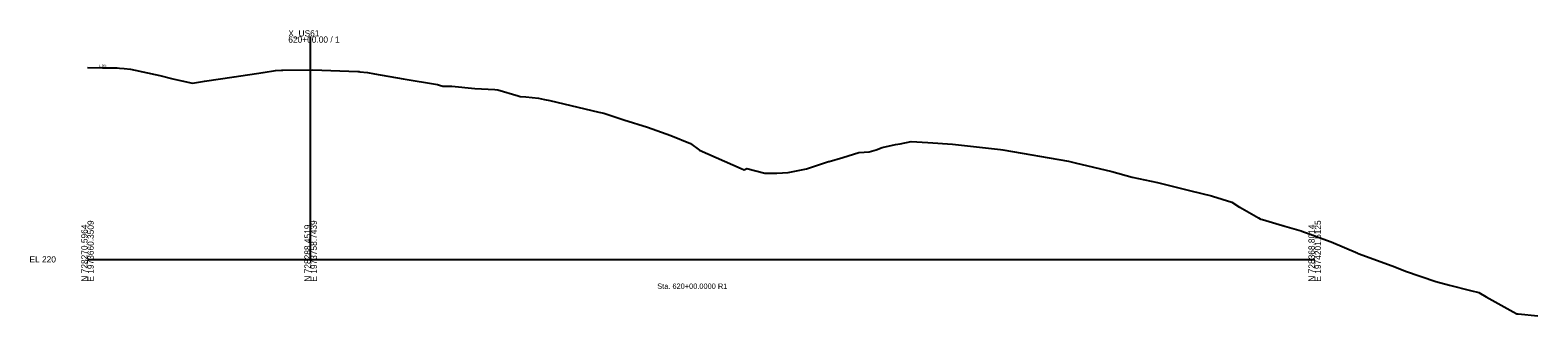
# Model space of a CAD drawing. Extents: x -26 to 1629, y -25 to 9635.
# Drawn here: x -26 to 650, y -25 to 103 of the extents above; entities that cross this region are included whole.
import ezdxf

# ---------------------------------------------------------------- set-up
doc = ezdxf.new("R2010")
doc.units = 0
for name, color, linetype in [('Draft_XS_Grid', 7, 'Continuous'), ('Draft_XS_Text', 7, 'Continuous'), ('DTM_X_GROUND', 7, 'Continuous'), ('XS_CELL', 7, 'Continuous'), ('XS_P_TX_FS_BS', 7, 'Continuous')]:
    doc.layers.add(name, color=color, linetype=linetype)

msp = doc.modelspace()

# ---------------------------------------------------------------- linework, layer by layer
at = {"layer": 'DTM_X_GROUND'}
msp.add_lwpolyline([(0, 86.07), (6.68, 85.98), (13.24, 85.89), (14.35, 85.8), (16.46, 85.62), (19.21, 85.29), (32.39, 82.46), (38.27, 80.96), (42.32, 80.06), (47.01, 79.01), (52.47, 79.87), (65.74, 81.91), (78.78, 83.88), (84.28, 84.67), (87.02, 84.81), (87.05, 84.81), (87.39, 84.82), (87.58, 84.82), (101, 84.97), (121.13, 84.25), (121.87, 84.23), (122.03, 84.2), (125.45, 83.77), (128.59, 83.2), (141.43, 80.94), (156.8, 78.42), (157.75, 78.22), (159.32, 77.75), (163.32, 77.65), (173.67, 76.59), (182.5, 76.21), (183.95, 76.1), (193, 73.37), (193.88, 73.12), (196.49, 72.84), (202.19, 72.31), (204.85, 71.74), (207.22, 71.23), (229.16, 66.09), (231.46, 65.52), (240.39, 62.54), (251.02, 59.35), (261.51, 55.61), (270.3, 52.01), (274.34, 48.95), (292.99, 40.79), (294.27, 40.2), (295.5, 40.7), (303.55, 38.64), (308.93, 38.73), (313.98, 38.95), (322.2, 40.64), (332.03, 43.83), (332.21, 43.88), (332.28, 43.9), (332.41, 43.95), (338.45, 45.74), (345.64, 47.87), (345.83, 47.89), (350.34, 48.27), (353.53, 49.09), (356.14, 50.15), (362.19, 51.47), (364.23, 51.88), (369.19, 52.88), (376.65, 52.47), (387.74, 51.7), (405.09, 49.76), (409.14, 49.3), (410.3, 49.16), (439.61, 44.08), (442.61, 43.3), (459.15, 39.38), (468.22, 36.93), (479.47, 34.46), (480.8, 34.13), (485.53, 32.98), (493.95, 30.92), (499.39, 29.6), (503.78, 28.53), (504.18, 28.41), (512.86, 25.63), (516.28, 23.47), (516.47, 23.37), (524.79, 18.6), (525.51, 18.2), (525.85, 18.05), (526.66, 17.83), (535.6, 15.24), (535.66, 15.23), (536.67, 14.94), (543.93, 12.79), (545.04, 12.4), (546.25, 11.93), (553.67, 9.18), (557.37, 7.88), (569.26, 2.72), (569.32, 2.7), (569.37, 2.68), (569.85, 2.5), (585.96, -3.4), (590.7, -5.29), (604.35, -9.98), (610.35, -11.62), (619.86, -13.96), (623.49, -14.81), (626.8, -16.78), (638.95, -23.52), (640.61, -24.46), (641.23, -24.51), (650, -25.36)], dxfattribs=at)
at = {"layer": 'XS_CELL'}
for p, q in [((100, 0), (100, 100)), ((0, 0), (100, 0)), ((100, 0), (550, 0))]:
    msp.add_line(p, q, dxfattribs=at)

# ---------------------------------------------------------------- texts
at = {"layer": 'Draft_XS_Grid'}
msp.add_text('-', height=0.0001, dxfattribs=at).set_placement((0, 0))
at = {"layer": 'Draft_XS_Text'}
msp.add_text('Sta. 620+00.0000 R1', height=2.4, dxfattribs=at).set_placement((255.34, -13.25))
at = {"layer": 'XS_CELL'}
for s, p in [('X_US61', (90, 100)), ('620+00.00 / 1', (90, 97.2)), ('EL 220', (-26, -1.4))]:
    msp.add_text(s, height=2.8, dxfattribs=at).set_placement(p)
for s, p in [('N 728270.5964', (0, -10)), ('E 1973660.3509', (2.8, -10)), ('N 728288.4519', (100, -10)), ('E 1973758.7439', (102.8, -10)), ('N 728368.8014', (550, -10)), ('E 1974201.5125', (552.8, -10))]:
    msp.add_text(s, height=2.8, rotation=90, dxfattribs=at).set_placement(p)
at = {"layer": 'XS_P_TX_FS_BS'}
msp.add_text('1.3%', height=1.08, rotation=359.22925, dxfattribs=at).set_placement((5.14, 86.3))

doc.saveas('drawing.dxf')
